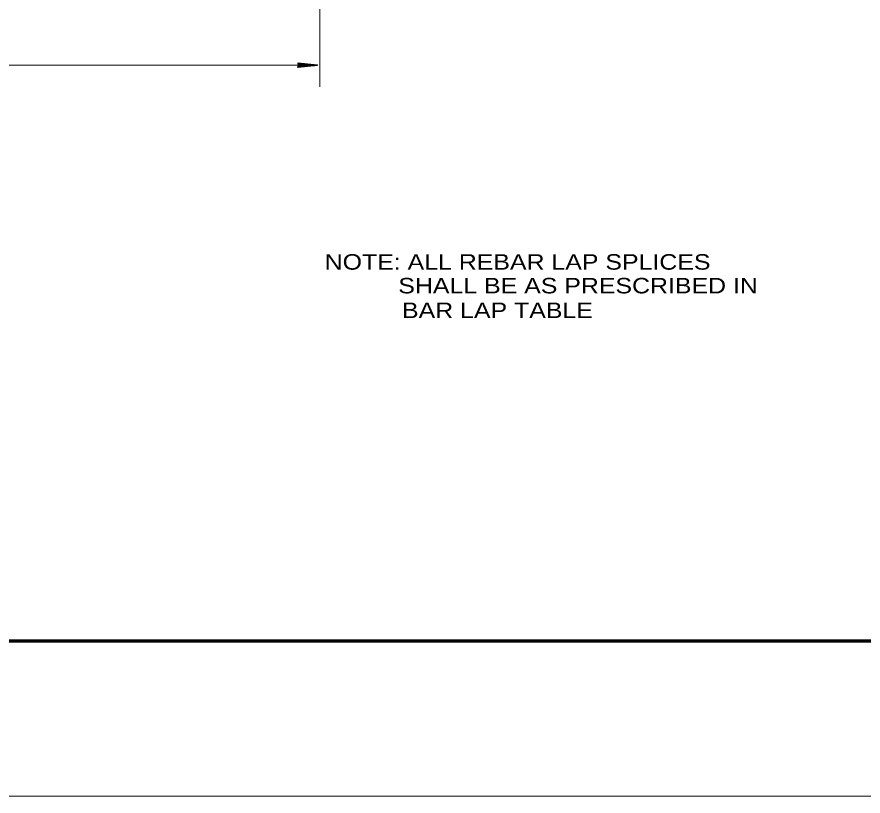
# Model space of a CAD drawing. Extents: x 3.64 to 6.84, y -0.8 to 1.19.
# Drawn here: x 4.5316 to 4.9864, y -0.7947 to -0.376 of the extents above; entities that cross this region are included whole.
import ezdxf

# ---------------------------------------------------------------- set-up
doc = ezdxf.new("R2010")
doc.units = 0
doc.header["$LTSCALE"] = 0.0033
doc.layers.add('1', color=7, linetype='Continuous', lineweight=40)

msp = doc.modelspace()

# ---------------------------------------------------------------- linework, layer by layer
at = {"layer": '1', "lineweight": 13}
for p, q in [((4.694417, -0.22875), (4.694417, -0.413667)), ((4.327667, -0.401917), (4.693083, -0.401917)), ((6.841583, -0.794667), (3.644833, -0.794667))]:
    msp.add_line(p, q, dxfattribs=at)
at = {"layer": '1', "lineweight": 35}
for p, q in [((4.6825, -0.401917), (4.693083, -0.401917)), ((4.682667, -0.402583), (4.69, -0.401833)), ((4.68275, -0.400917), (4.690583, -0.401833)), ((4.68275, -0.400917), (4.690583, -0.401833)), ((4.68275, -0.401), (4.690583, -0.401833)), ((4.68275, -0.401083), (4.690583, -0.401917)), ((4.68275, -0.401083), (4.690583, -0.402083)), ((4.68275, -0.40275), (4.690083, -0.401917)), ((4.68275, -0.402833), (4.690083, -0.402083)), ((4.68275, -0.403), (4.690083, -0.402167))]:
    msp.add_line(p, q, dxfattribs=at)
at = {"layer": '1', "lineweight": 70}
msp.add_line((3.811583, -0.711333), (6.75825, -0.711333), dxfattribs=at)
at = {"layer": '1'}
msp.add_lwpolyline([(3.811583, -0.711333), (6.17325, -0.711333), (6.17325, -0.38625), (6.75825, -0.38625)], dxfattribs=at)
at = {"layer": '1', "lineweight": 35}
for points in [[(4.6825, -0.400833), (4.693083, -0.401917), (4.6825, -0.403083), (4.683083, -0.401917)], [(4.68325, -0.401833), (4.687917, -0.40175), (4.687917, -0.401833), (4.687, -0.401833), (4.68325, -0.40175), (4.68625, -0.401667), (4.683083, -0.401583), (4.685333, -0.4015), (4.683083, -0.401417), (4.686583, -0.401667), (4.69125, -0.401833), (4.690333, -0.402083), (4.691583, -0.402083), (4.68325, -0.402083), (4.685667, -0.40225), (4.683083, -0.40225), (4.688417, -0.401833), (4.683083, -0.4025)]]:
    msp.add_lwpolyline(points, close=True, dxfattribs=at)
msp.add_lwpolyline([(4.68325, -0.401833), (4.682833, -0.401083), (4.683083, -0.401333), (4.68325, -0.401667), (4.6835, -0.401583), (4.683333, -0.40125), (4.683167, -0.402), (4.683, -0.4025), (4.68275, -0.402917)], dxfattribs=at)

# ---------------------------------------------------------------- texts
at = {"layer": '1', "width": 1.2}
for s, p in [('NOTE: ALL REBAR LAP SPLICES', (4.697, -0.511833)), ('SHALL BE AS PRESCRIBED IN', (4.736583, -0.524583)), ('BAR LAP TABLE', (4.738583, -0.537833))]:
    msp.add_text(s, height=0.008334, dxfattribs=at).set_placement(p)

doc.saveas('drawing.dxf')
